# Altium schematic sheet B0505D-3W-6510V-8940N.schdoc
size 277 x 190 mm; Device: default297x210; Symbol: default297x210; Name: default297x210; Rev: V1.0; Size: "A4"; Id: /; Sheet: /; File: B0505D-3W-6510V-8940N
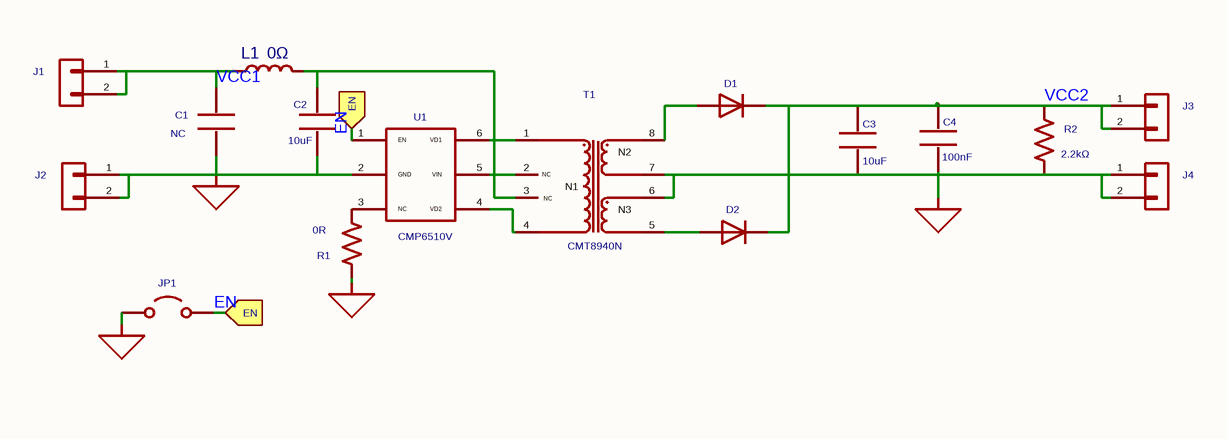
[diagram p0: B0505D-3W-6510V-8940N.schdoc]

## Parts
C1  value NC  [MYLibrary:C0603]  (hidden comment: My_Library_C)
C2  10uF  [MYLibrary:C0603]
C3  10uF  [MYLibrary:C0603]
C4  100nF  [MYLibrary:C0603]
D1  DSS34  [MYLibrary:SOD-123-323]  (value not drawn)
D2  DSS34  [MYLibrary:SOD-123-323]  (value not drawn)
J1  HX PZ2.54-1x2P ZZ  [Connector_PinHeader_2.54mm:PinHeader_1x02_P2.54mm_Vertical]  (value not drawn)
J2  HX PZ2.54-1x2P ZZ  [Connector_PinHeader_2.54mm:PinHeader_1x02_P2.54mm_Vertical]  (value not drawn)
J3  HX PZ2.54-1x2P ZZ  [Connector_PinHeader_2.54mm:PinHeader_1x02_P2.54mm_Vertical]  (value not drawn)
J4  HX PZ2.54-1x2P ZZ  [Connector_PinHeader_2.54mm:PinHeader_1x02_P2.54mm_Vertical]  (value not drawn)
JP1  HX PZ2.54-1x2P ZZ  [Connector_PinHeader_2.54mm:PinHeader_1x02_P2.54mm_Vertical]  (value not drawn)
L1  0Ω  [Inductor_SMD:L_1206_3216Metric]
R1  value 0R  [MYLibrary:R0603]  (hidden comment: My_Library_R)
R2  2.2kΩ  [MYLibrary:R0603]
T1  value CMT8940N  [CMT8940N-1]  (hidden comment: MYLibrary _CMT8830U)
U1  CMP6510V  [MYLibrary:SOT23-6]

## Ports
EN (in)

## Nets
GND1: C1.1 C2.1 J2.1(Pin_1) J2.2(Pin_2) JP1.1(A) R1.1 U1.2(GND)
GND2: C3.1 C4.1 J4.1(Pin_1) J4.2(Pin_2) R2.2 T1.6 T1.7
EN: JP1.2(B) U1.1(EN) ; port EN
VCC1: C1.2 J1.1(Pin_1) J1.2(Pin_2) L1.1
VCC2: C3.2 C4.2 D1.1(K) D2.1(K) J3.1(Pin_1) J3.2(Pin_2) R2.1
NetC2_2: C2.2 L1.2 T1.2 T1.3 U1.5(VIN)
NetD1_2: D1.2(A) T1.8
NetD2_2: D2.2(A) T1.5
NetR1_2: R1.2 U1.3(NC)
NetT1_1: T1.1 U1.6(VD1)
NetT1_4: T1.4 U1.4(VD2)

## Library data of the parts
C1 = My_Library_C: Add into BOM: no; ki_keywords: cap capacitor; ki_fp_filters: C_*; UniqueId: 5fb4f22ffcb6a001
C2 = 0603X106K100NT: 容值:10uF;精度:±10%;额定电压:10V;温度系数:X5R;; Manufacturer: FH(风华); Add into BOM: yes; Symbol: My_Library_C; 3D Model: ac125912035d415993ca9572d50418b1; 3D Model Transform: 62.992,31.496,0,0,0,0,0,0,0; Tolerance: ±10%; Voltage Rating: 10V; Temperature Coefficient: X5R; ki_keywords: cap capacitor; ki_fp_filters: C_*; UniqueId: 21d50210554cb61f; ModelName: C0603_L1.6-W0.8-H0.8
C3 = 0603X106K100NT: 容值:10uF;精度:±10%;额定电压:10V;温度系数:X5R;; Manufacturer: FH(风华); Add into BOM: yes; Symbol: My_Library_C; 3D Model: ac125912035d415993ca9572d50418b1; 3D Model Transform: 62.992,31.496,0,0,0,0,0,0,0; Tolerance: ±10%; Voltage Rating: 10V; Temperature Coefficient: X5R; ki_keywords: cap capacitor; ki_fp_filters: C_*; UniqueId: ec64484c8c07847f; ModelName: C0603_L1.6-W0.8-H0.8
C4 = CC0603KRX7R9BB104: 容值:100nF;精度:±10%;额定电压:50V;温度系数:X7R;; Manufacturer: YAGEO(国巨); Add into BOM: yes; Symbol: My_Library_C; 3D Model: ac125912035d415993ca9572d50418b1; 3D Model Transform: 62.992,31.496,0,0,0,0,0,0,0; Tolerance: ±10%; Voltage Rating: 50V; Temperature Coefficient: X7R; ki_keywords: cap capacitor; ki_fp_filters: C_*; UniqueId: 623e2bb2442f04df; ModelName: C0603_L1.6-W0.8-H0.8
D1 = DSS34_C511866: 正向压降(Vf):550mV@3A;直流反向耐压(Vr):40V;整流电流:3A;; Manufacturer: BORN(伯恩半导体); Symbol: My_Library_D; Add into BOM: yes; 3D Model: 86f9151e155e4fe2af0c4f2e0a80302e; 3D Model Transform: 141.732,70.866,0,180,0,0,0,0,0; Voltage - DC Reverse(Vr): 40V; Current - Rectified: 3A; Reverse Leakage Current (Ir): 500uA@40V; Operating Junction Temperature Range: -50℃~+125℃; Value: D; ki_keywords: diode; ki_fp_filters: TO-???* *_Diode_* *SingleDiode* D_*; UniqueId: 07a0d5848cd81316; ModelName: SOD-123FL_L2.8-W1.8-H1.1-LS3.6
D2 = DSS34_C511866: 正向压降(Vf):550mV@3A;直流反向耐压(Vr):40V;整流电流:3A;; Manufacturer: BORN(伯恩半导体); Symbol: My_Library_D; Add into BOM: yes; 3D Model: 86f9151e155e4fe2af0c4f2e0a80302e; 3D Model Transform: 141.732,70.866,0,180,0,0,0,0,0; Voltage - DC Reverse(Vr): 40V; Current - Rectified: 3A; Reverse Leakage Current (Ir): 500uA@40V; Operating Junction Temperature Range: -50℃~+125℃; Value: D; ki_keywords: diode; ki_fp_filters: TO-???* *_Diode_* *SingleDiode* D_*; UniqueId: fa5cd661465da5bc; ModelName: SOD-123FL_L2.8-W1.8-H1.1-LS3.6
J1 = HX PZ2.54-1x2P ZZ: 插针结构:1x2P;间距:2.54mm;行距:-;圆针/方针:方针;安装方式:直插;排数:单排;总PIN位数:2P;额定电流:3A;额定电压:1kV;配合针长度:6mm;塑高:2.5mm;端接针长度:3mm;触头材质:黄铜;触头镀层:金;工作温度:-40℃~+105℃;颜色:黑色;; Manufacturer: hanxia(韩下); Add into BOM: yes; Symbol: Connector_Generic_Conn_01x02; 3D Model: c7a9f3c3e6e34627af2bf939e464cb35; 3D Model Transform: 200,100,0,0,0,0,0,0,-118.11; Pin Structure: 1x2P; Pitch: 2.54mm; Circluar Pins/Square Pins: 方针; Current Rating: 3A; Voltage Rating (Max): 1kV; ki_keywords: connector; ki_fp_filters: Connector*:*_1x??_*; UniqueId: 9f49826860c2c79d; ModelName: HDR-TH_2P-P2.54-M-LI-1X2P
J2 = HX PZ2.54-1x2P ZZ: 插针结构:1x2P;间距:2.54mm;行距:-;圆针/方针:方针;安装方式:直插;排数:单排;总PIN位数:2P;额定电流:3A;额定电压:1kV;配合针长度:6mm;塑高:2.5mm;端接针长度:3mm;触头材质:黄铜;触头镀层:金;工作温度:-40℃~+105℃;颜色:黑色;; Manufacturer: hanxia(韩下); Add into BOM: yes; Symbol: Connector_Generic_Conn_01x02; 3D Model: c7a9f3c3e6e34627af2bf939e464cb35; 3D Model Transform: 200,100,0,0,0,0,0,0,-118.11; Pin Structure: 1x2P; Pitch: 2.54mm; Circluar Pins/Square Pins: 方针; Current Rating: 3A; Voltage Rating (Max): 1kV; ki_keywords: connector; ki_fp_filters: Connector*:*_1x??_*; UniqueId: 42913bc3a3449998; ModelName: HDR-TH_2P-P2.54-M-LI-1X2P
J3 = HX PZ2.54-1x2P ZZ: 插针结构:1x2P;间距:2.54mm;行距:-;圆针/方针:方针;安装方式:直插;排数:单排;总PIN位数:2P;额定电流:3A;额定电压:1kV;配合针长度:6mm;塑高:2.5mm;端接针长度:3mm;触头材质:黄铜;触头镀层:金;工作温度:-40℃~+105℃;颜色:黑色;; Manufacturer: hanxia(韩下); Add into BOM: yes; Symbol: Connector_Generic_Conn_01x02; 3D Model: c7a9f3c3e6e34627af2bf939e464cb35; 3D Model Transform: 200,100,0,0,0,0,0,0,-118.11; Pin Structure: 1x2P; Pitch: 2.54mm; Circluar Pins/Square Pins: 方针; Current Rating: 3A; Voltage Rating (Max): 1kV; ki_keywords: connector; ki_fp_filters: Connector*:*_1x??_*; UniqueId: 6ca7fcf0d18ad80e; ModelName: HDR-TH_2P-P2.54-M-LI-1X2P
J4 = HX PZ2.54-1x2P ZZ: 插针结构:1x2P;间距:2.54mm;行距:-;圆针/方针:方针;安装方式:直插;排数:单排;总PIN位数:2P;额定电流:3A;额定电压:1kV;配合针长度:6mm;塑高:2.5mm;端接针长度:3mm;触头材质:黄铜;触头镀层:金;工作温度:-40℃~+105℃;颜色:黑色;; Manufacturer: hanxia(韩下); Add into BOM: yes; Symbol: Connector_Generic_Conn_01x02; 3D Model: c7a9f3c3e6e34627af2bf939e464cb35; 3D Model Transform: 200,100,0,0,0,0,0,0,-118.11; Pin Structure: 1x2P; Pitch: 2.54mm; Circluar Pins/Square Pins: 方针; Current Rating: 3A; Voltage Rating (Max): 1kV; ki_keywords: connector; ki_fp_filters: Connector*:*_1x??_*; UniqueId: 048fde32f53a6793; ModelName: HDR-TH_2P-P2.54-M-LI-1X2P
JP1 = HX PZ2.54-1x2P ZZ: 插针结构:1x2P;间距:2.54mm;行距:-;圆针/方针:方针;安装方式:直插;排数:单排;总PIN位数:2P;额定电流:3A;额定电压:1kV;配合针长度:6mm;塑高:2.5mm;端接针长度:3mm;触头材质:黄铜;触头镀层:金;工作温度:-40℃~+105℃;颜色:黑色;; Manufacturer: hanxia(韩下); Add into BOM: yes; Symbol: Jumper_Jumper_2_Open; 3D Model: c7a9f3c3e6e34627af2bf939e464cb35; 3D Model Transform: 200,100,0,0,0,0,0,0,-118.11; Pin Structure: 1x2P; Pitch: 2.54mm; Circluar Pins/Square Pins: 方针; Current Rating: 3A; Voltage Rating (Max): 1kV; ki_keywords: Jumper SPST; ki_fp_filters: Jumper* TestPoint*2Pads* TestPoint*Bridge*; UniqueId: 3f7cd319db4ef0a6; ModelName: HDR-TH_2P-P2.54-M-LI-1X2P
L1 = RC1206FR-070RL: 电阻类型:厚膜电阻;阻值:0Ω;精度:±1%;功率:250mW;工作电压:200V;; Manufacturer: YAGEO(国巨); Add into BOM: yes; Symbol: Device_L; 3D Model: 89a1f13db2384da588040e0b3c55bf66; 3D Model Transform: 125.984,62.992,0,0,0,0,0,0,0; Type: 厚膜电阻; Tolerance: ±1%; Power(Watts): 250mW; Voltage-Supply(Max): 200V; ki_keywords: inductor choke coil reactor magnetic; ki_fp_filters: Choke_* *Coil* Inductor_* L_*; UniqueId: 2f42939b1ffc8518; ModelName: R1206_L3.2-W1.6-H0.6
R1 = My_Library_R: Add into BOM: no; ki_keywords: R res resistor; ki_fp_filters: R_*; UniqueId: 4e166b190d4de1c3
R2 = RC0603FR-072K2L: 电阻类型:厚膜电阻;阻值:2.2kΩ;精度:±1%;功率:100mW;工作电压:75V;温度系数:±100ppm/℃;; Manufacturer: YAGEO(国巨); Add into BOM: yes; Symbol: My_Library_R; 3D Model: fc143cca1e79419f9cd78b61e9279f08; 3D Model Transform: 31.8897,63.7794,0,90,0,0,0,0,0; Tolerance: ±1%; Power(Watts): 100mW; Voltage-Supply(Max): 75V; ki_keywords: R res resistor; ki_fp_filters: R_*; UniqueId: 06442d24ab060343; ModelName: R0603
T1 = MYLibrary _CMT8940N: Origin Footprint: MYLibrary:CMT8830U; UniqueId: cf2c480e5945250c; Attribute1: T1; AddInBom: yes
U1 = CMP6510V: CMP6510V 是推挽式变压器驱动器，芯片内部集成一对 N 型功率 MOSFET，通过内部振荡器提供具有精准时序和死区时间的互补驱动信号。驱动器搭配配套的变压器，可以实现输入电压 3.3V/5V, 输出功率不超过 2W 的隔离电源。采用不同的变压器，外围只需搭配简单的二极管，即可获得 3.3V-24V 的非稳压输出。芯片内置软启动、过流保护、过温保护、欠压保护等多种保护功能。; Manufacturer: coileasy(线易); Add into BOM: yes; 3D Model: 18da8f6c14a34920b3e136b5c401a119; 3D Model Transform: 110.73671,114.173,0,180,0,0,0.001,-0.003,0; Symbol: My_Library_VPS8504B; Origin Footprint: library:VPS8504B; UniqueId: 48a4a086d8c42a18; ModelName: SOT-23-6_L2.9-W1.6-H1.5-LS2.8-P0.95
